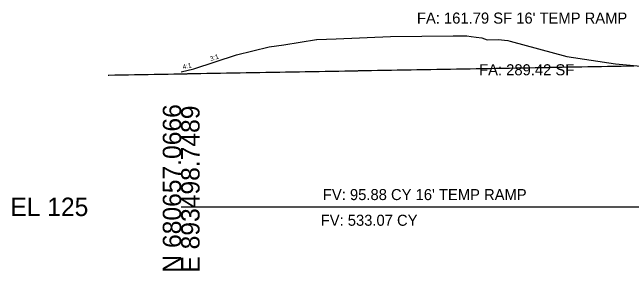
# Model space of a CAD drawing. Extents: x -26 to 4303, y -13 to 10775.
# Drawn here: x -25.7 to 68.6, y 9490.3 to 9529.6 of the extents above; entities that cross this region are included whole.
import ezdxf

# ---------------------------------------------------------------- set-up
doc = ezdxf.new("R2010")
doc.units = 0
for name, color, linetype in [('Draft_XS_Grid', 7, 'Continuous'), ('DTM_P_FINISHED_GRADE', 7, 'Continuous'), ('DTM_X_GROUND', 7, 'Continuous'), ('XS_CELL', 7, 'Continuous'), ('XS_M_SHAPES_EARTHWORK', 7, 'Continuous'), ('XS_P_TX_FS_BS', 7, 'Continuous'), ('XS_SHEET_EW_TX_VOLUME', 7, 'Continuous')]:
    doc.layers.add(name, color=color, linetype=linetype)

msp = doc.modelspace()

# ---------------------------------------------------------------- linework, layer by layer
at = {"layer": 'DTM_P_FINISHED_GRADE'}
msp.add_lwpolyline([(-11.103, 9520.036), (-11, 9520.038), (-10.103, 9520.053), (-10, 9520.055), (-9.103, 9520.071), (-9, 9520.073), (-8.103, 9520.088), (-8, 9520.09), (-7.103, 9520.106), (-7, 9520.108), (-6.103, 9520.123), (-6, 9520.125), (-5.103, 9520.141), (-5, 9520.143), (-4.103, 9520.158), (-4, 9520.16), (-3.103, 9520.176), (-3, 9520.178), (-2.103, 9520.193), (-2, 9520.195), (-1.103, 9520.211), (-1, 9520.213), (-0.103, 9520.228), (0, 9520.23), (0.897, 9520.246), (1, 9520.248), (1.897, 9520.263), (2, 9520.265), (2.897, 9520.281), (3, 9520.283), (3.897, 9520.298), (4, 9520.3), (4.897, 9520.316), (5, 9520.318), (5.897, 9520.333), (6, 9520.335), (6.897, 9520.351), (7, 9520.353), (7.897, 9520.368), (8, 9520.37), (8.897, 9520.386), (9, 9520.388), (9.897, 9520.403), (10, 9520.405), (10.897, 9520.421), (11, 9520.423), (11.897, 9520.438), (12, 9520.44), (12.897, 9520.456), (13, 9520.458), (13.897, 9520.473), (14, 9520.475), (14.897, 9520.491), (15, 9520.493), (15.897, 9520.508), (16, 9520.51), (16.897, 9520.526), (17, 9520.528), (17.897, 9520.543), (18, 9520.545), (18.897, 9520.561), (19, 9520.563), (19.897, 9520.578), (20, 9520.58), (20.897, 9520.596), (21, 9520.598), (21.897, 9520.613), (22, 9520.615), (22.897, 9520.631), (23, 9520.633), (23.897, 9520.648), (24, 9520.65), (24.897, 9520.666), (25, 9520.668), (25.897, 9520.683), (26, 9520.685), (26.897, 9520.701), (27, 9520.703), (27.897, 9520.718), (28, 9520.72), (28.897, 9520.736), (29, 9520.738), (29.897, 9520.753), (30, 9520.755), (30.897, 9520.771), (31, 9520.773), (31.897, 9520.788), (32, 9520.79), (32.897, 9520.806), (33, 9520.808), (33.897, 9520.823), (34, 9520.825), (34.897, 9520.841), (35, 9520.843), (35.897, 9520.858), (36, 9520.86), (36.897, 9520.876), (37, 9520.878), (37.897, 9520.893), (38, 9520.895), (38.897, 9520.911), (39, 9520.913), (39.897, 9520.928), (40, 9520.93), (40.897, 9520.946), (41, 9520.948), (41.897, 9520.963), (42, 9520.965), (42.897, 9520.981), (43, 9520.983), (43.897, 9520.998), (44, 9521), (44.897, 9521.016), (45, 9521.018), (45.897, 9521.033), (46, 9521.035), (46.897, 9521.051), (47, 9521.053), (47.897, 9521.068), (48, 9521.07), (48.897, 9521.086), (49, 9521.088), (49.897, 9521.103), (50, 9521.105), (50.897, 9521.121), (51, 9521.123), (51.897, 9521.138), (52, 9521.14), (52.897, 9521.156), (53, 9521.158), (53.897, 9521.173), (54, 9521.175), (54.897, 9521.191), (55, 9521.193), (55.897, 9521.208), (56, 9521.21), (56.897, 9521.226), (57, 9521.228), (57.897, 9521.243), (58, 9521.245), (58.897, 9521.261), (59, 9521.263), (59.897, 9521.278), (60, 9521.28), (60.897, 9521.296), (61, 9521.298), (61.897, 9521.313), (62, 9521.315), (62.897, 9521.331), (63, 9521.333), (63.897, 9521.348), (64, 9521.35), (64.897, 9521.366), (65, 9521.368), (65.897, 9521.383), (66, 9521.385), (66.897, 9521.401), (67, 9521.403), (67.897, 9521.418), (68, 9521.42), (68.897, 9521.436)], dxfattribs=at)
at = {"layer": 'DTM_X_GROUND'}
msp.add_lwpolyline([(0, 9520.524), (1.92, 9520.967), (8.419, 9523.109), (13.407, 9524.345), (15.631, 9524.625), (20.592, 9525.442), (20.646, 9525.447), (23.573, 9525.567), (31.847, 9525.912), (41.412, 9525.978), (43.488, 9525.993), (44.133, 9525.872), (44.921, 9525.794), (45.792, 9525.71), (46.601, 9525.411), (48.238, 9525.433), (49.751, 9525.268), (50.092, 9525.209), (58.726, 9522.847), (66.099, 9521.734), (71.648, 9521.239)], dxfattribs=at)
at = {"layer": 'XS_CELL'}
msp.add_line((0, 9500), (150, 9500), dxfattribs=at)

# ---------------------------------------------------------------- texts
at = {"layer": 'Draft_XS_Grid'}
msp.add_text('-', height=0.0001, dxfattribs=at).set_placement((0, 9500))
at = {"layer": 'XS_CELL'}
for s, p in [('N 680657.0666', (0, 9490)), ('E 893498.7489', (2.8, 9490))]:
    msp.add_text(s, height=2.8, rotation=90, dxfattribs=at).set_placement(p)
msp.add_text('EL 125', height=2.8, dxfattribs=at).set_placement((-26, 9498.6))
at = {"layer": 'XS_M_SHAPES_EARTHWORK'}
for s, p in [("FV: 95.88 CY 16' TEMP RAMP", (21.578, 9501.025)), ('FV: 533.07 CY', (21.245, 9497.12))]:
    msp.add_text(s, height=1.68, dxfattribs=at).set_placement(p)
at = {"layer": 'XS_P_TX_FS_BS'}
for s, rotation, p in [('3:1', 18.23637, (4.494, 9522.131)), ('4:1', 13.00083, (0.296, 9520.9))]:
    msp.add_text(s, height=0.72, rotation=rotation, dxfattribs=at).set_placement(p)
at = {"layer": 'XS_SHEET_EW_TX_VOLUME'}
for s, p in [("FA: 161.79 SF 16' TEMP RAMP", (35.894, 9527.855)), ('FA: 289.42 SF', (45.357, 9520))]:
    msp.add_text(s, height=1.68, dxfattribs=at).set_placement(p)

doc.saveas('drawing.dxf')
